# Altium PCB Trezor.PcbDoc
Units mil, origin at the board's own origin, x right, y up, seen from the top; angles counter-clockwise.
Board outline 4000 x 3600 mil, 2 copper layers (Top, Bottom), stack 62 mil thick; 38 components, 17 nets, 131 pads, 2 vias.
Unrouted connection lines stored in the file: 20.
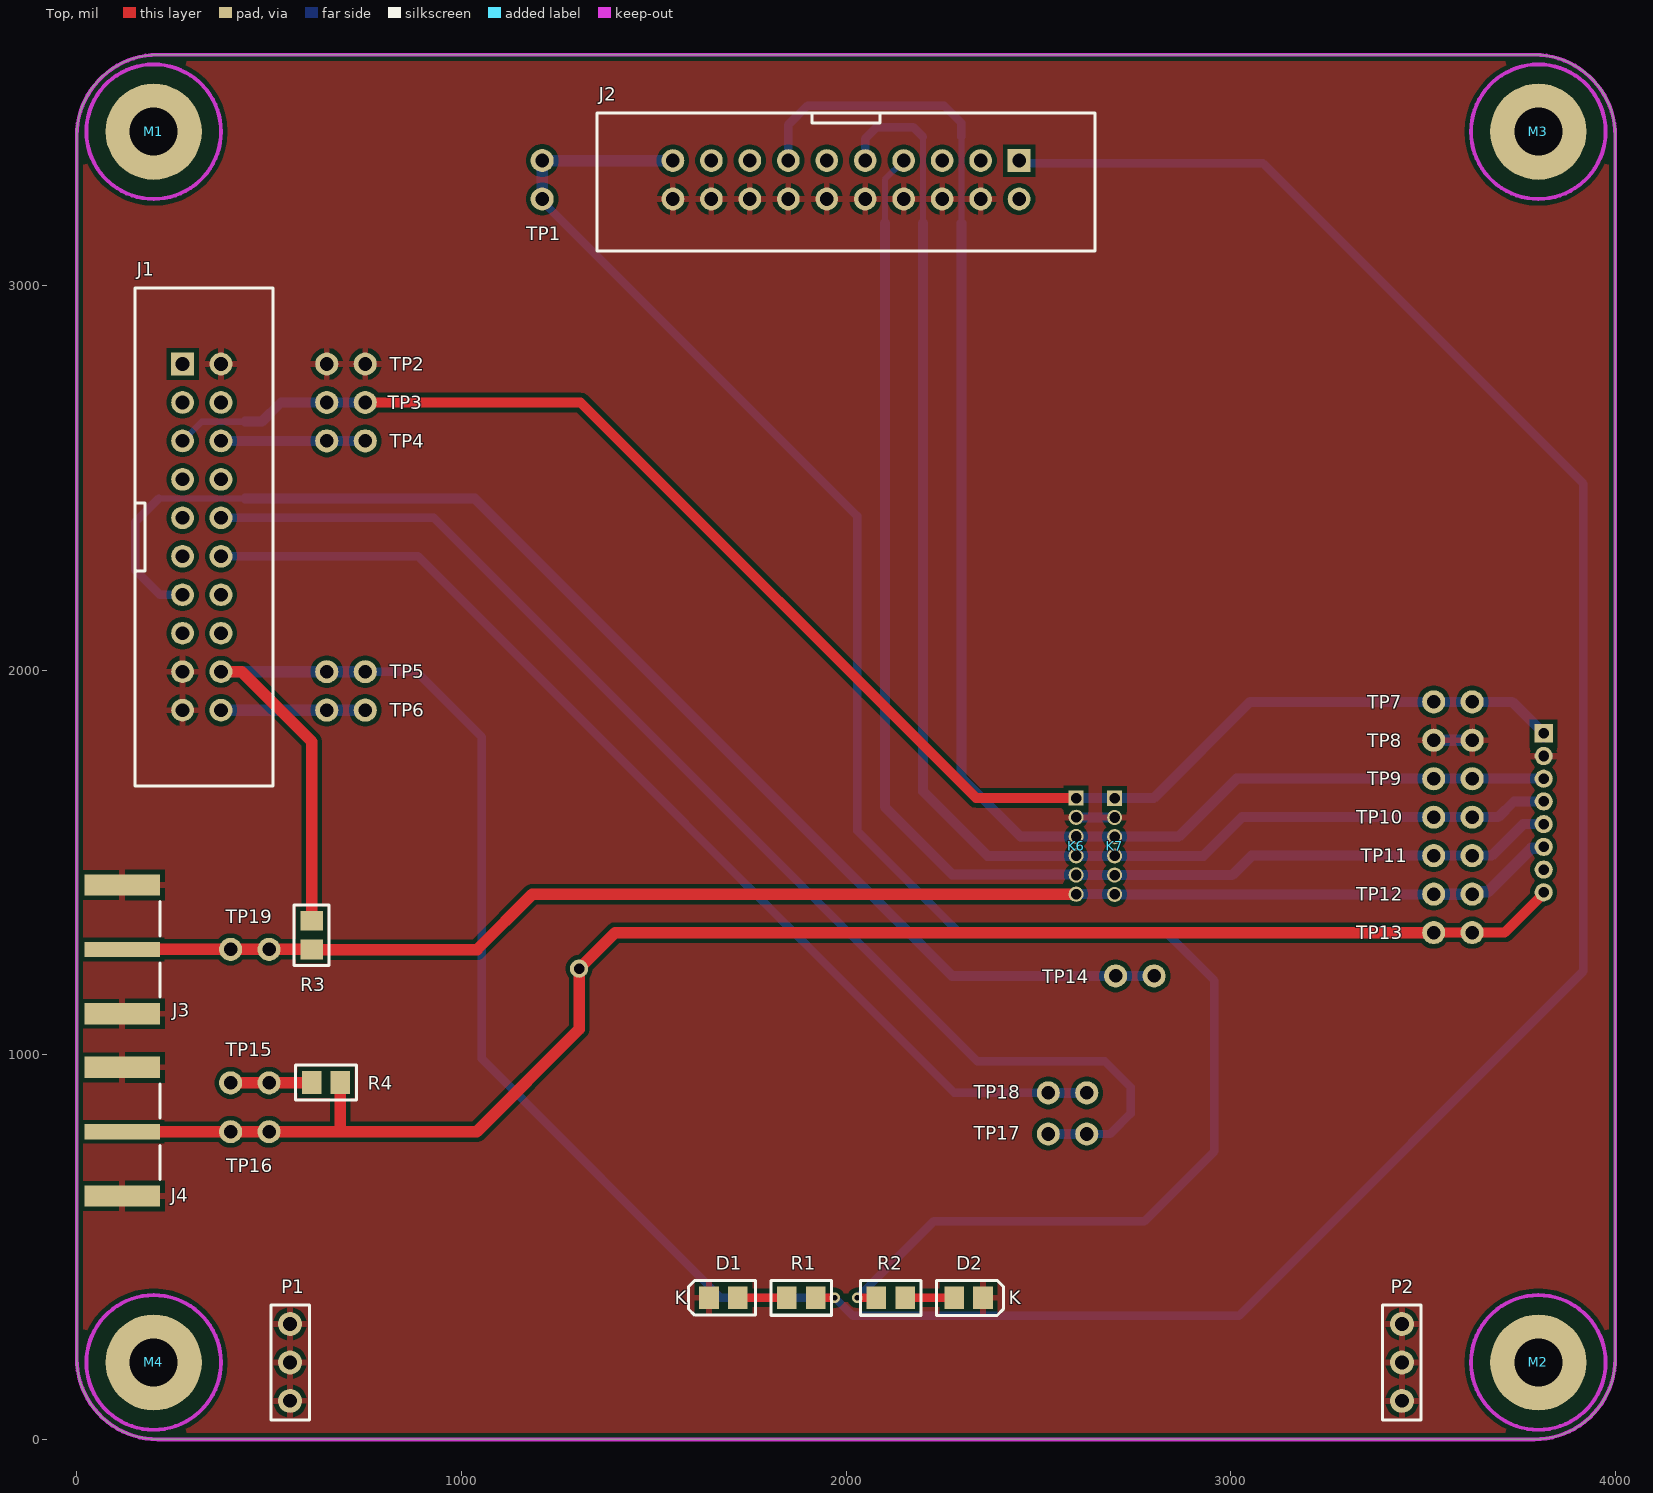
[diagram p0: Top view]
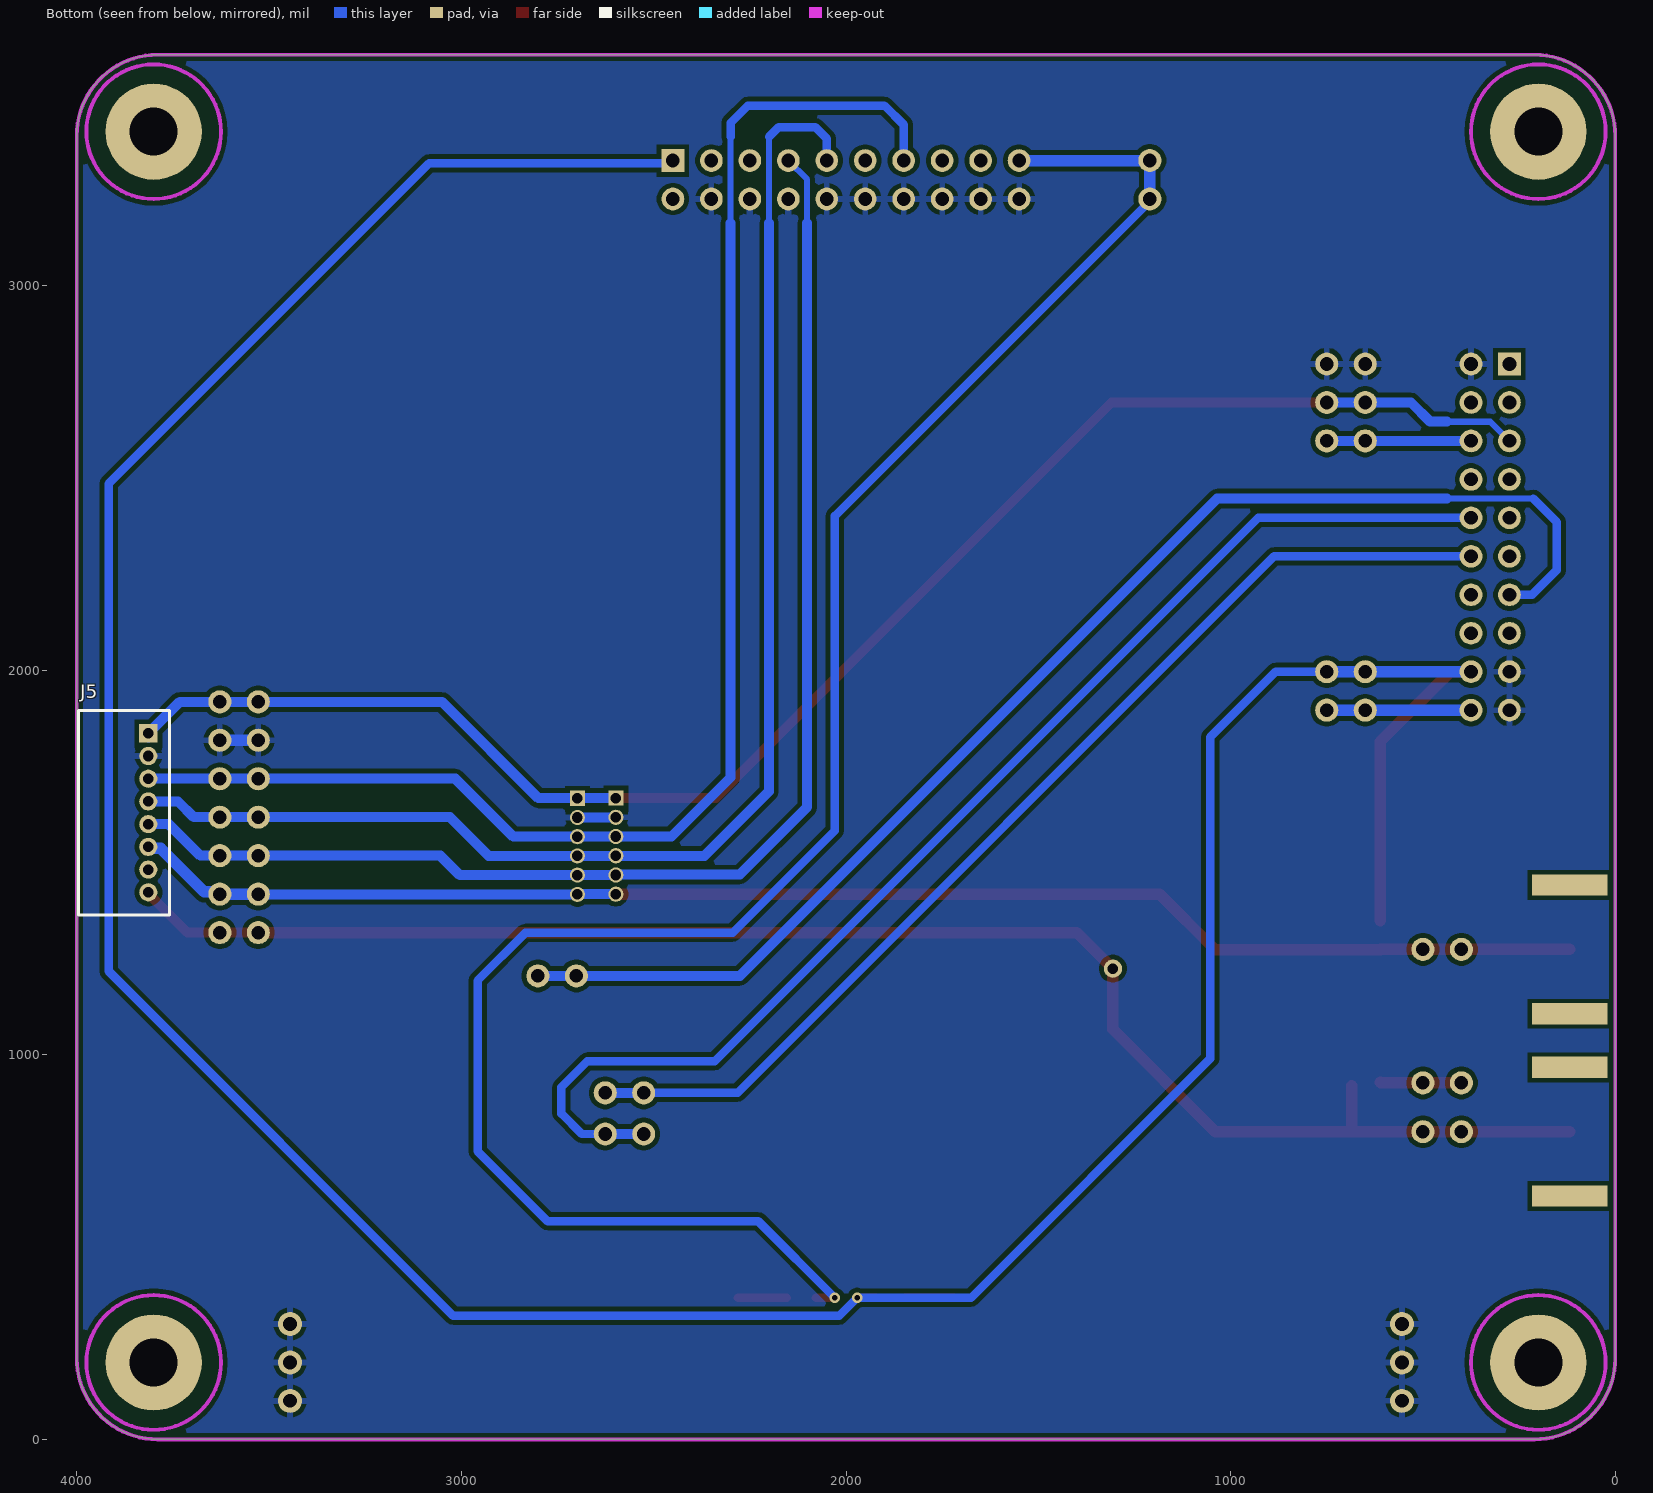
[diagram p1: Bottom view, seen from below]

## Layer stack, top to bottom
Top Solder: solder mask 0.4, Solder Resist, Dk 3.5
Top: signal copper 1.4
Dielectric1: core 59.2, FR-4, Dk 4.8
Bottom: signal copper 1.4
Bottom Solder: solder mask 0.4, Solder Resist, Dk 3.5

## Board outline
0,210 0,3390 cw(c210,3390) 210,3600 3790,3600 cw(c3790,3390) 4000,3390 4000,210 cw(c3790,210) 3790,0 210,0 cw(c210,210)

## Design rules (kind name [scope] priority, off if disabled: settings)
Clearance Clearance_1 [InPolygon] p1: gap=12 ignorepadtopadclearanceinfootprint=FALSE except(0: Arc-Hole Track-Hole SMDPad-Hole THPad-Hole Via-Hole Fill-Hole Poly-Hole Region-Hole Text-Hole)
Clearance [All] p2: gap=10 ignorepadtopadclearanceinfootprint=FALSE
ComponentClearance [All] p1 off: gap=0 collisioncheckmode=3 verticalgap=10 showdistances=FALSE
FabricationTestPointUsage TestPointUsage [All] p1: valid=0 allowmultiple=FALSE
FabricationTestpoint Testpoint [All] p1: side=3 testpointundercomponent=TRUE minsize=40 maxsize=100 preferedsize=60 minholesize=0 maxholesize=40 preferedholesize=32 testpointgrid=1 allowsidetop=TRUE allowsidebottom=TRUE usegrid=TRUE gridtolerance=0.01
HoleSize [All] p1: absolutevalues=TRUE maxlimit=250 minlimit=10 maxpercent=80.000 minpercent=20.000
MinimumAnnularRing [All] p1: minimumring=5
PlaneClearance [All] p1: clearance=12
PlaneConnect [All] p1: planeconnectstyle=Relief reliefexpansion=12 reliefentries=4 reliefconductorwidth=12 reliefairgap=12
PolygonConnect [IsVia] p1: connectstyle=Direct reliefconductorwidth=10 reliefentries=4 polygonreliefangle="90 Angle" airgapwidth=10
PolygonConnect PolygonConnect_1 [All] p2: connectstyle=Relief reliefconductorwidth=16 reliefentries=4 polygonreliefangle="90 Angle" airgapwidth=12
RoutingVias [All] p1: holewidth=14 width=28 viastyle="Through Hole" minholewidth=14 minwidth=28 maxholewidth=14 maxwidth=28
SilkToSolderMaskClearance SilkscreenOverComponentPads [IsPad] p1: minsilkscreentomaskgap=10 clearancetoexposedcopper=TRUE
SolderMaskExpansion SolderMaskExpansion_1 [(IsVia)] p1: expansion=-14 istentingtop=FALSE
SolderMaskExpansion [All] p2: expansion=4 istentingtop=FALSE
SupplyNets "Schematic Supply Nets_3" [InNet('3V3_CW')] p1: voltage=0.000
SupplyNets "Schematic Supply Nets_2" [InNet('GND')] p2: voltage=0.000
SupplyNets "Schematic Supply Nets_1" [InNet('5V0_JLINK')] p3: voltage=0.000
SupplyNets "Schematic Supply Nets" [InNet('5V0_CW')] p4: voltage=0.000
Width [All] p1: maxlimit=32 minlimit=12 preferedwidth=12 minimp=50.000000 maximp=50.000000 favimp=50.000000
23 further rules are at their usual default settings.

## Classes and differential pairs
component class Trezor: D1 D2 J1 J2 J3 J5 P1 P2 R1 R2 R3 TP1 TP2 TP3 TP4 TP5 TP6 TP7 TP8 TP9 TP10 TP11 TP12 TP13 TP14 TP15 TP16 TP17 TP18 TP19

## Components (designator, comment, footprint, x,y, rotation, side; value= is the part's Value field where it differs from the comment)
D1 "LED" "CC2012-0805 LED" 1681.26,368 r180 top
D2 "LED" "CC2012-0805 LED" 2318.76,368 r0 top
J1 "N2520-6002-RB" "HDR2X10 - SHROUD" 275,2796 r270 top locked
J2 "N2520-6002-RB" "HDR2X10 - SHROUD" 2450,3325 r180 top locked
J3 "32K145-400L5" ROS-32K145-400L5_V 20,1274 r90 top locked
J4 "32K145-400L5" ROS-32K145-400L5_V 20,800 r90 top locked
J5 "JST S8B-ZR" JST-S8B-ZR 3814,1422.42 r90 bottom locked
K6 "SWD" SWD 2598.33,1667.43 r270 top locked
K7 "SWD" SWD 2698.33,1667 r270 top locked
M1 "Comment" MOUNTING-HOLE-4-40 200,3400 r0 top
M2 "Comment" MOUNTING-HOLE-4-40 3800,200 r0 top
M3 "Comment" MOUNTING-HOLE-4-40 3800,3400 r0 top
M4 "Comment" MOUNTING-HOLE-4-40 200,200 r0 top
P1 "Header 3" HEADER3 554.5,300 r270 top locked
P2 "Header 3" HEADER3 3445.5,300 r270 top locked
R1 "Res1" CC2012-0805 1883.76,368 r180 top value=10k
R2 "Res1" CC2012-0805 2116.26,368 r0 top value=10k
R3 "Res1" CC2012-0805 610.6,1311 r270 top value="10 ohm"
R4 "Res1" CC2012-0805 648,928 r0 top value=DNP
TP1 "TESTPOINT" "TESTPOINT - DOUBLE"#1 1210,3325 r270 top
TP2 "TESTPOINT" "TESTPOINT - DOUBLE"#1 650,2796 r0 top
TP3 "TESTPOINT" "TESTPOINT - DOUBLE"#1 650,2696 r0 top
TP4 "TESTPOINT" "TESTPOINT - DOUBLE"#1 650,2596 r0 top
TP5 "TESTPOINT" "TESTPOINT - DOUBLE"#1 650,1996 r0 top
TP6 "TESTPOINT" "TESTPOINT - DOUBLE"#1 750,1896 r180 top
TP7 "TESTPOINT" "TESTPOINT - DOUBLE"#1 3528,1917.69 r0 top
TP8 "TESTPOINT" "TESTPOINT - DOUBLE"#1 3528,1817.69 r0 top
TP9 "TESTPOINT" "TESTPOINT - DOUBLE"#1 3528,1717.69 r0 top
TP10 "TESTPOINT" "TESTPOINT - DOUBLE"#1 3528,1617.69 r0 top
TP11 "TESTPOINT" "TESTPOINT - DOUBLE"#1 3528,1517.69 r0 top
TP12 "TESTPOINT" "TESTPOINT - DOUBLE"#1 3528,1417.69 r0 top
TP13 "TESTPOINT" "TESTPOINT - DOUBLE"#1 3528,1317.69 r0 top
TP14 "TESTPOINT" "TESTPOINT - DOUBLE"#1 2701,1205 r0 top
TP15 "TESTPOINT" "TESTPOINT - DOUBLE"#1 400,927 r0 top
TP16 "TESTPOINT" "TESTPOINT - DOUBLE"#1 400,800 r0 top
TP17 "TESTPOINT" "TESTPOINT - DOUBLE"#1 2526,794 r0 top
TP18 "TESTPOINT" "TESTPOINT - DOUBLE"#1 2526,901 r0 top
TP19 "TESTPOINT" "TESTPOINT - DOUBLE"#2 400,1272 r0 top

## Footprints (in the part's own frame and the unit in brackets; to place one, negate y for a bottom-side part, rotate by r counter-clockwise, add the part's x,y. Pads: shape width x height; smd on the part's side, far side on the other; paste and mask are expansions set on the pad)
CC2012-0805 [mm]
  rect 1.3x1.5 smd: 1(-0.95,0) 2(0.95,0)
  silkscreen extent -2,-1.15 2,1.15
"CC2012-0805 LED" [mm]
  rect 1.3x1.5 smd: 1(-0.95,0) 2(0.95,0)
  silkscreen extent -2.12,-1.16 2.3,1.14
"HDR2X10 - SHROUD" [mm] "3M N2520-6002-RB CONN HEADER VERT 20POS 2.54MM"
  rect 1.5x1.5 hole 0.9: 1(0,0)
  round 1.5 hole 0.9: 2(0,2.54) 3(2.54,0) 4(2.54,2.54) 5(5.08,0) 6(5.08,2.54) 7(7.62,0) 8(7.62,2.54) 9(10.16,0) 10(10.16,2.54) 11(12.7,0) 12(12.7,2.54) 13(15.24,0) 14(15.24,2.54) 15(17.78,0) 16(17.78,2.54) 17(20.32,0) 18(20.32,2.54) 19(22.86,0) 20(22.86,2.54)
  silkscreen extent -5.02,-3.13 27.88,5.97
HEADER3 [mil]
  round 62 hole 35.43: 1(0,0) 2(100,0) 3(200,0)
  silkscreen extent -50,-50 250,50
JST-S8B-ZR [mm]
  rect 1.2x1.2 hole 0.7: 1(10.5,0)
  round 1.2 hole 0.7: 2(9,0) 3(7.5,0) 4(6,0) 5(4.5,0) 6(3,0) 7(1.5,0) 8(0,0)
  silkscreen extent -1.5,-1.4 12,4.6
MOUNTING-HOLE-4-40 [mil] "Mounting Hole w/ Annular Ring US #4-40/Metric M3"
  round 250 hole 125: 0(0,0)
  Keep-Out Layer circle w10: c0,0 r175
ROS-32K145-400L5_V [mm] "SMA Right Angle Jack, Edge Mount, 14.25x9.5x4.46mm, Rosenberger Recommended"
  rect 1x5 smd: 1(0,-2.5)
  rect 1.4x5 smd: MP(-4.25,-2.5) MP(4.25,-2.5)
  rect 1.4x5 smd far side paste-2: ""(-4.25,-2.5) ""(4.25,-2.5)
  silkscreen extent -3.15,-5 3.15,-5, body extent -4.75,-4.75 4.75,9.5, height 4.46
SWD [mm]
  rect 1x1 hole 0.7 paste-2539.97 mask+0.102: 1(0,0)
  round 1 hole 0.7 paste-2539.97 mask+0.102: 2(1.27,0) 3(2.54,0) 4(3.81,0) 5(5.08,0) 6(6.35,0)
"TESTPOINT - DOUBLE"#1 [mil]
  round 60 hole 35.43: 1(0,0) 1(100,0)
"TESTPOINT - DOUBLE"#2 [mil]
  round 60 hole 35.43: 1(0,2) 1(100,2)

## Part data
D1 D2: library part LED0, "Typical LED"
J1 J2: library part "Header 10X2", "Header, 10-Pin, Dual row"
J3 J4: "SMA Right Angle Jack, Edge Mount, Up to 18 GHz, -55 to 155 degC"
J5: library part "Header 8", "Header, 8-Pin"
P1 P2: "Header, 3-Pin"
R1 R2 R3 R4: "Resistor"

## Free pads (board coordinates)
  round 47.56 hole 27.56: 6(1306,1224)

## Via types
v1: diameter 28, hole 14, Top to Bottom, 2 vias

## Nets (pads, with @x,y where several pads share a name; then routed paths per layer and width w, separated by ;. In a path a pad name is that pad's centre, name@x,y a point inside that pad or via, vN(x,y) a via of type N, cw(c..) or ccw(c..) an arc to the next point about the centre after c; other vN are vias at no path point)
3V3_CW: J1.18 J2.1 R1.1 R3.1 TP5.1 | length 9003
  Top w22: R1.1 v1(1971.01,368)
  Top w30: J1.18 429,1996 610.6,1814.4 R3.1
  Bottom w22: TP5.1@750,1996 883,1996 1053,1826 1053,990 1675,368 v1@1969.39,368 ; v1(1971.01,368) 2018.01,321 3021,321 3917,1217 3917,2485 3085.18,3316.82 ; J2.1 2457,3318 3084,3318
  Bottom w30: J1.18 650,1996 TP5.1@750,1996
5V0_CW: J1.20 TP6.1 | length 375
  Bottom w30: J1.20 650,1896 TP6.1@750,1896
5V0_JLINK: J2.19 R2.1 TP1.1 | length 5087.5
  Top w22: v1(2029,368) R2.1
  Bottom w22: TP1.1@1210,3220 2029,2401 2029,1583 2295,1317 2834,1317 2958,1193 2958,749 2776,567 2228,567 v1(2029,368)
  Bottom w30: TP1.1@1210,3225 1210,3325 1260,3325 J2.19
GND: D1.2 D2.2 J1.2 J1.17 J1.19 J2.4 J2.6 J2.8 J2.10 J2.12 J2.14 J2.16 J2.18 J2.20 J3.MP J4.MP J5.2 K6.2 K7.2 P1.1 P1.2 P1.3 P2.1 P2.2 P2.3 TP2.1 TP8.1 | length 199.6
  Bottom w26: K6.2 K7.2@2697.9,1617.43
  Bottom w30: TP8.1@3528,1817.69 TP8.1@3628,1817.69
HS2: J1.6 TP4.1 | length 375
  Bottom w26: J1.6 650,2596 TP4.1@750,2596
NetD1_1: D1.1 R1.2 | length 127.7
  Top w22: D1.1 R1.2
NetD2_1: D2.1 R2.2 | length 127.7
  Top w22: R2.2 D2.1
NetR4_1: R4.1 TP15.1 | length 211
  Top w30: TP15.1@400,927 500,927 609.6,927 R4.1
NRST: J1.5 J5.1 K6.1 K7.1 TP3.1 TP7.1 | length 4152.5
  Top w26: TP3.1@750,2696 1310,2696 2338.57,1667.43 K6.1
  Bottom w16: J1.5 325,2646 437,2646
  Bottom w26: 437,2646 481,2646 531,2696 650,2696 TP3.1@750,2696 ; K6.1 2697.9,1667.43 K7.1 2800,1667 3050.69,1917.69 3628,1917.69 3732.11,1917.69 J5.1 ; J5.1@3808.29,1830.09 J5.1@3814,1824.39
PDIC: J1.13 TP14.1 | length 3465.9
  Top w22: J1.13@272.79,2193.79 J1.13
  Bottom w16: 213,2446 437,2446
  Bottom w22: 213,2446 152,2385 152,2260 216,2196 J1.13
  Bottom w26: 437,2446 469,2446 1035,2446 2276,1205 2701,1205 TP14.1@2801,1205
SCA_3V3: J3.1 J5.6 K6.6 K7.6 R3.2 TP12.1 TP19.1 | length 3806.5
  Top w30: J3.1 400,1274 500,1274 R3.2@609.6,1274 ; R3.2 1040.79,1273.6 1184.62,1417.43 K6.6
  Bottom w26: K6.6 K7.6@2697.9,1417.43 ; K7.6 TP12.1@3523.31,1417 ; TP12.1@3523.31,1413 TP12.1@3528,1417.69
  Bottom w30: TP12.1@3528,1417.69 3628,1417.69 3633.69,1423.38 3668.38,1423.38 3782.23,1537.23 3810.7,1537.23 J5.6
SCA_VCORE: J4.1 J5.8 pad.6 R4.2 TP13.1 TP16.1 | length 4164.7
  Top w26: TP13.1@3528,1317.69 3628,1317.69 3712.69,1317.69 J5.8@3814,1419
  Top w30: J4.1 400,800 500,800 685,800 ; R4.2@685.4,920 685.4,800.4 685,800 ; TP13.1@3528,1317.69 1399.69,1317.69 pad.6 1306,1066 1040,800 685,800
SWCLK: J2.9 J5.4 K6.4 K7.4 TP10.1 | length 3673.4
  Bottom w16: 2200,3163 2200,3387
  Bottom w22: J2.9 2050,3382 2080,3412 2175,3412 2200,3387
  Bottom w26: 2200,3163 2200,3131 2200,1685 2367.57,1517.43 K6.4 K7.4@2697.9,1517.43 ; K7.4 2929,1517 3029.69,1617.69 3628,1617.69 3695.69,1617.69 3736.64,1658.64 J5.4
SWDIO: J2.7 J5.5 K6.5 K7.5 TP11.1 | length 3541.9
  Bottom w16: 2101,3163 2101,3276 J2.7
  Bottom w26: 2101,3163 2101,1644 2276,1469 2596.76,1469 K6.5 K7.5@2697.9,1467.43 ; K7.5 3004,1467 3054.69,1517.69 3628,1517.69 3678.69,1517.69 3760.58,1599.58 J5.5
SWO: J2.13 J5.3 K6.3 K7.3 TP9.1 | length 3928.6
  Top w26: TP9.1@3628,1717.69 TP9.1@3631.31,1721
  Bottom w16: 2300,3163 2300,3387
  Bottom w22: J2.13 1850,3418 1900,3468 2255,3468 2300,3423 2300,3387
  Bottom w26: 2300,3163 2300,3131 2300,1721 2453.57,1567.43 K6.3 K7.3@2697.9,1567.43 ; K7.3 2865,1567 3015.69,1717.69 3628,1717.69 J5.3
TIO1: J1.10 TP17.1 | length 3283
  Bottom w22: J1.10 928.42,2396 2341.71,982.71 2673.29,982.71 2740,916 2740,847 2687,794 TP17.1@2626,794
  Bottom w26: TP17.1@2526,794 TP17.1@2626,794
TIO2: J1.12 TP18.1 | length 2828.8
  Bottom w22: J1.12 887,2296 2282,901 TP18.1@2526,901
  Bottom w26: TP18.1@2526,901 TP18.1@2626,901
pads on no net: J1.1 J1.3 J1.4 J1.7 J1.8 J1.9 J1.11 J1.14 J1.15 J1.16 J2.2 J2.3 J2.5 J2.11 J2.15 J2.17 J3. J4. J5.7 M1.0 M2.0 M3.0 M4.0

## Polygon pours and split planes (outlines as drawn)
GND on Bottom "GND_L02_P001" (solid, remove dead copper, pour order 3): 0,3600 4000,3600 4000,0 0,0
GND on Top "GND_L01_P001" (solid, remove dead copper, pour order 4): 0,3600 4000,3600 4000,0 0,0

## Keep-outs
Keep-Out Layer:
  the board outline again, w10

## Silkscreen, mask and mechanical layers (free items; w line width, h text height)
Top Overlay:
  text "K" at 1554.76,351 h35
  text "K" at 2423.76,351 h35
Silkscreen Top:
  lines w8: 2629.2,2311.01 cw(c2629.2,2391.01) 2549.2,2391.01 2549.2,2700.26 cw(c2629.2,2700.26) 2629.2,2780.26 ; 2629.2,2311.01 2665.26,2311.01 2665.26,1433.89 2610.14,1183.89 2557,1209.48 2486.13,1059.87 2539.28,1034.28 2503.85,987.04 2436.92,967.35 2358.18,845.3 2358.18,790.18 2270.58,609.08 2179.83,609.08 2179.83,794.64 1820.2,794.64 1820.2,609.08 1729.24,609.08 1643.61,786.25 1641.64,790.18 1641.64,845.3 1562.9,967.35 1495.97,987.04 1460.54,1034.28 1513.69,1059.87 1442.82,1209.48 1389.67,1183.89 1334.55,1433.89 1334.55,2892.55 cw(c1373.92,2892.55) 1373.92,2931.92 1645.58,2931.92 1645.58,2857.11 ccw(c1665.26,2857.11) 1665.26,2837.43 2334.55,2837.43 ccw(c2334.55,2857.11) 2354.24,2857.11 2354.24,2931.92 2625.89,2931.92 cw(c2625.89,2892.55) 2665.26,2892.55 2665.26,2780.26 2629.2,2780.26 ; 2629.2,2311.01 2629.2,2311.01 ; 2629.2,2780.26 2629.2,2780.26
  text "J-LINK" at 2726,3174 h35 r90
  text "J-LINK" at 1114,3115 h35
  text "+5V" at 1158,3043 h35
  text "CW" at 294,3037 h35
  text "GND" at 831,2778 h35
  text "NRST" at 831,2678 h35
  text "HS2" at 831,2578 h35
  text "CW" at 831,1978 h35
  text "+3." at 925.87,1977.77 h35
  text "3V" at 1014,1977.77 h35
  text "NRST" at 3312.93,1900.69 h35
  text "CW +5V" at 831,1878 h35
  text "GND" at 3347.92,1800.69 h35
  text "TDO/SWO" at 3207.97,1700.69 h35
  text "TCK/SWDCLK" at 3103,1600.69 h35
  text "TMS/SWDIO" at 3143.82,1500.69 h35
  text "VDD" at 3347.92,1400.69 h35
  text "SCA +3.3V" at 694,1332 h35
  text "Glitch Out" at 3132.16,1300.69 h35
  text "BOOT0" at 2882,1183 h35
  text "SCA VCORE" at 395,1004 h35
  text "PA10/RX" at 2707,883.51 h35
  text "Glitch In" at 578,783 h35
  text "PA9/TX" at 2707,776.51 h35
  text "CW" at 1658.13,435.23 h35
  text "+3." at 1753,435 h35
  text "3V" at 1841,435 h35
  text "J-LINK +5V" at 2051,435 h35
  text "GND" at 508,385 h35
  text "GND" at 3398,385 h35
  text "Trezor Model T In-Situ Adapter" at 1352,126 h90
Silkscreen Bottom:
  text "Joe Grand (@joegrand)" at 2353,181 h35
  text "Lennert Wouters (@lennertwo)" at 2463.8,99 h35
Board Shape:
  the board outline again, w10
Drill Drawing:
  drawing of 1722 lines, arcs and shapes, not listed
  text "FABRICATION / ASSEMBLY NOTES:" at 69.17,6847 h59.06
  text "(UNLESS OTHERWISE SPECIFIED)" at 69.17,6747 h59.06
  text "1. MATERIAL: EPOXY GLASS LAMINATE FR-4" at 69.17,6547 h59.06
  text "FINISHED COPPER WEIGHT SHALL BE 1 OZ ON ALL LAYERS" at 169.17,6447 h59.06
  text "2. NUMBER OF ELECTRICAL LAYERS: 2" at 69.17,6247 h59.06
  text "3. THICKNESS: 0.062\" (FINISHED)" at 73.17,6047 h59.06
  text "4. FINISH: IMMERSION PLATE EXPOSED AREAS AFTER APPLYING SOLDER MASK WITH ELECTROLESS NICKEL IMMERSION GOLD" at 75,5839 h59.06
  text "5. SOLDER MASK: LIQUID PHOTOIMAGEABLE SOLDER MASK PER IPC-SM-840" at 75,5639 h59.06
  text "COLOR ANY, 10/ 50um THK, BOTH SIDES, AFTER PLATING. REGISTRATION TO BE WITHIN +/- 50um" at 190,5539 h59.06
  text "OF THE ASSOCIATED CIRCUIT LAYER." at 190,5439 h59.06
  text "6. SILKSCREEN: SILKSCREEN BOTH SIDES USING WHITE NONCONDUCTIVE INK." at 75,5239 h59.06
  text "7. BARE BOARD ELECTRICAL TEST: 100% SCHEMATIC NETLIST TEST COVERAGE REQUIRED." at 75,5039 h59.06
  text "8. RoHS: PARTS SHALL BE RoHS COMPLIANT PER EUROPEAN UNION DIRECTIVE 2002/95/EC." at 75,4839 h59.06
  text "9. THE BOARD MUST BE LEAD-FREE ASSEMBLY PROCESS COMPATIBLE AND BE ABLE TO HANDLE A MINIMUM" at 75,4639 h59.06
  text "OF 5 CYCLES AT 260 DEGREES CELSIUS" at 198,4539 h59.06
  text "10. NO QA/QC/TEST/FAB MARKINGS ANYWHERE ON THE PCB" at 75,4339 h59.06
  text ".PCB_FILE_NAME_NO_PATH" at -905.7,-955.88 h70
  text "COMPANY:" at 922.71,-1181.75 h39.37
  text "Grand Idea Studio, Inc." at 1058.75,-1310 h49.21
  text "TITLE:" at 922.71,-1496.71 h39.37
  text "Trezor One In-Situ Adapter Board" at 1058.75,-1621 h49.21
  text "DRAWN:" at 922.71,-1811.67 h39.37
  text "Joe Grand" at 1058.75,-1933 h49.21
  text "DESIGN FILES DISTRIBUTED UNDER A" at -792.08,-1939.39 h34.45
  text "CREATIVE COMMONS ATTRIBUTION 4.0 INTERNATIONAL LICENSE" at -792.08,-2018.13 h34.45
  text "2024 cc by 4.0" at -796.33,-2101.28 h34.45
  text "ISSUE:" at 922.71,-2126.63 h39.37
  text "DATE:" at 1395.16,-2126.63 h39.37
  text ".PRINT_DATE" at 1691.3,-2148.88 h49.21
  text "A" at 1192.3,-2154.88 h49.21
  text ".LEGEND" at 3028,-2186 h60

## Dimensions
3790,3600 to 3790,0 on Drill Drawing
0,3390 to 4000,3390 on Drill Drawing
